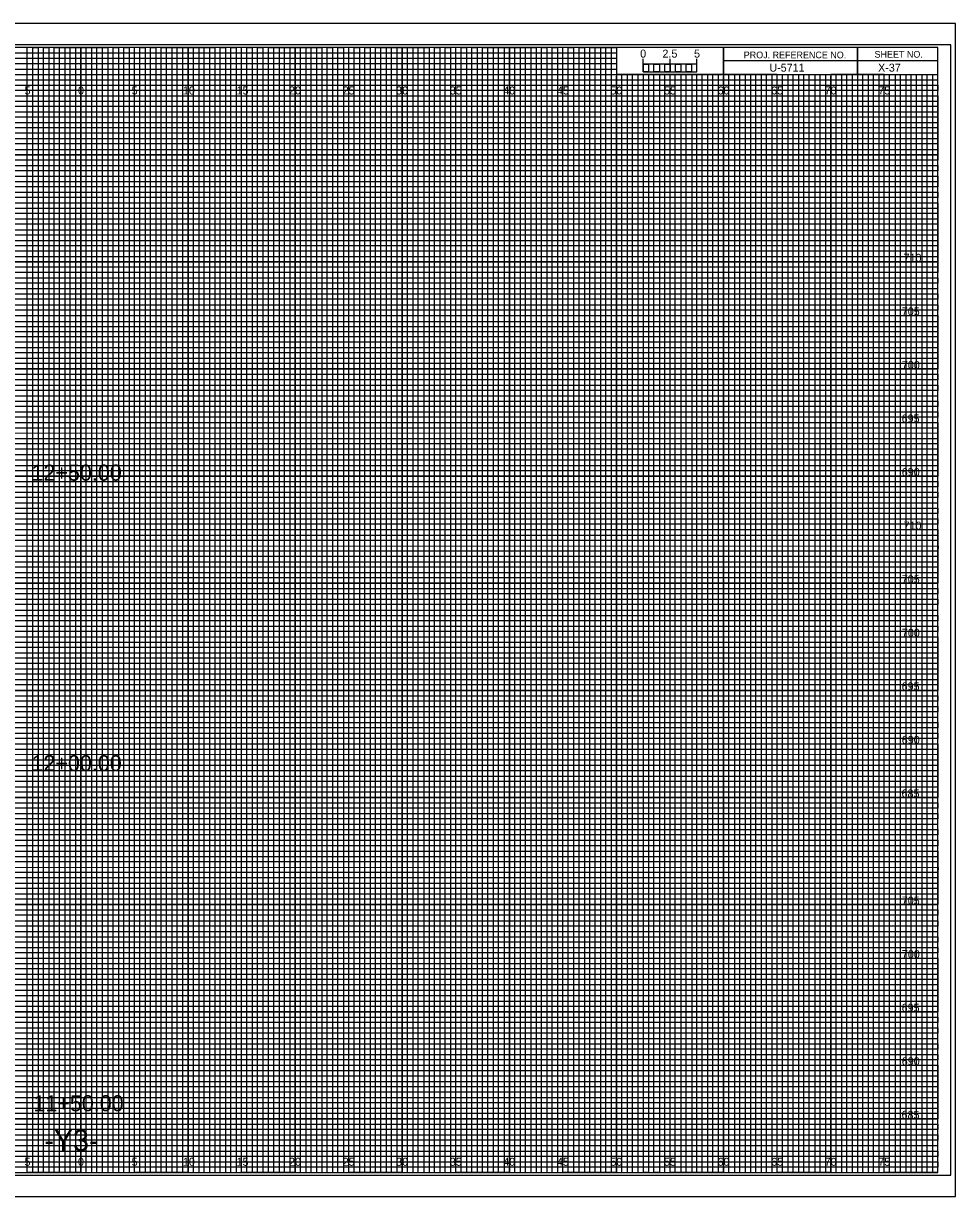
# Model space of a CAD drawing. Extents: x -7 to 162, y 108 to 217.
# Drawn here: x 74.6 to 161.7, y 107.8 to 217.2 of the extents above; entities that cross this region are included whole.
import ezdxf

# ---------------------------------------------------------------- set-up
doc = ezdxf.new("R2010")
doc.units = 0
for name, color, linetype in [('Exist Cross Section Cell', 7, 'Continuous'), ('Exist XS Ground Line', 7, 'Continuous'), ('Prop CMT Pvmt Course 1', 7, 'Continuous'), ('Prop CMT Pvmt Course 2', 7, 'Continuous'), ('Prop CMT Pvmt Course 3', 7, 'Continuous'), ('Prop CMT Pvmt Surface', 7, 'Continuous'), ('Prop CMT Pvmt Surface Shoulder', 7, 'Continuous'), ('Prop CMT Shld Paved Course 1', 7, 'Continuous'), ('Prop CMT Shld Paved Course 2', 7, 'Continuous'), ('Prop CMT Shld Paved Course 3', 7, 'Continuous'), ('Prop CMT Slope Grass', 7, 'Continuous'), ('Prop CMT Subgrade Earthwork', 7, 'Continuous'), ('Prop XS Ditch Standard Text', 7, 'Continuous'), ('Prop XS SE Text', 7, 'Continuous'), ('Prop XS Side Slope Text', 7, 'Continuous'), ('Scratch_Level_7', 7, 'Continuous'), ('Scratch_Level_8', 7, 'Continuous')]:
    doc.layers.add(name, color=color, linetype=linetype)

msp = doc.modelspace()

# ---------------------------------------------------------------- linework, layer by layer
at = {"layer": 'Exist XS Ground Line'}
for p, q in [((75, 215), (70, 215)), ((75, 110), (75, 215)), ((85, 215), (80, 215)), ((80, 215), (80, 110)), ((85, 110), (85, 215)), ((95, 215), (90, 215)), ((90, 215), (90, 110)), ((95, 110), (95, 215)), ((105, 215), (100, 215)), ((100, 215), (100, 110)), ((105, 110), (105, 215)), ((115, 215), (110, 215)), ((110, 215), (110, 110)), ((115, 110), (115, 215)), ((125, 215), (120, 215)), ((120, 215), (120, 110)), ((125, 110), (125, 215)), ((130, 215), (130, 110)), ((135, 110), (135, 212.5)), ((145, 212.5), (140, 212.5)), ((140, 212.5), (140, 110)), ((145, 110), (145, 212.5)), ((155, 212.5), (150, 212.5)), ((150, 212.5), (150, 110)), ((155, 110), (155, 212.5)), ((80, 110), (75, 110)), ((90, 110), (85, 110)), ((100, 110), (95, 110)), ((110, 110), (105, 110)), ((120, 110), (115, 110)), ((130, 110), (125, 110)), ((140, 110), (135, 110)), ((150, 110), (145, 110)), ((160, 110), (155, 110)), ((160, 110), (160, 110))]:
    msp.add_line(p, q, dxfattribs=at)
for points in [[(0, 210), (160, 210), (160, 205), (0, 205)], [(0, 200), (160, 200), (160, 195), (0, 195)], [(0, 190), (160, 190), (160, 185), (0, 185)], [(0, 180), (160, 180), (160, 175), (0, 175)], [(0, 170), (160, 170), (160, 165), (0, 165)], [(0, 160), (160, 160), (160, 155), (0, 155)], [(0, 150), (160, 150), (160, 145), (0, 145)], [(0, 140), (160, 140), (160, 135), (0, 135)], [(0, 130), (160, 130), (160, 125), (0, 125)], [(0, 120), (160, 120), (160, 115), (0, 115)]]:
    msp.add_lwpolyline(points, dxfattribs=at)
at = {"layer": 'Prop CMT Pvmt Course 2'}
for p, q in [((132.5, 212.75), (132.5, 213.95)), ((132.5, 213.45), (132.5, 213.95)), ((135, 212.75), (135, 213.95)), ((137.5, 212.75), (137.5, 213.95)), ((137.5, 213.45), (137.5, 213.95))]:
    msp.add_line(p, q, dxfattribs=at)
for points in [[(137.5, 213.45), (132.5, 213.45), (132.5, 212.75), (137.5, 212.75)], [(132.5, 213.45), (133, 213.45), (133, 212.75), (132.5, 212.75)], [(133.5, 213.45), (134, 213.45), (134, 212.75), (133.5, 212.75)], [(134.5, 213.45), (135, 213.45), (135, 212.75), (134.5, 212.75)], [(135.5, 213.45), (136, 213.45), (136, 212.75), (135.5, 212.75)], [(136.5, 213.45), (137, 213.45), (137, 212.75), (136.5, 212.75)]]:
    msp.add_lwpolyline(points, close=True, dxfattribs=at)
at = {"layer": 'Prop CMT Pvmt Course 3'}
msp.add_lwpolyline([(-6.7, 107.75), (161.65, 107.75), (161.65, 217.25), (-6.7, 217.25)], close=True, dxfattribs=at)
at = {"layer": 'Prop CMT Pvmt Surface'}
for p, q in [((75, 110), (75, 215)), ((80, 110), (80, 215)), ((85, 110), (85, 215)), ((90, 110), (90, 215)), ((95, 110), (95, 215)), ((100, 110), (100, 215)), ((105, 110), (105, 215)), ((110, 110), (110, 215)), ((115, 110), (115, 215)), ((120, 110), (120, 215)), ((125, 110), (125, 215)), ((130, 110), (130, 212.34)), ((135, 110), (135, 212.34)), ((140, 110), (140, 212.34)), ((145, 110), (145, 212.34)), ((150, 110), (150, 212.34)), ((155, 110), (155, 212.34)), ((0, 210), (160, 210)), ((0, 205), (160, 205)), ((0, 200), (160, 200)), ((0, 195), (160, 195)), ((0, 190), (160, 190)), ((0, 185), (160, 185)), ((0, 180), (160, 180)), ((0, 175), (160, 175)), ((0, 170), (160, 170)), ((0, 165), (160, 165)), ((0, 160), (160, 160)), ((0, 155), (160, 155)), ((0, 150), (160, 150)), ((0, 145), (160, 145)), ((0, 140), (160, 140)), ((0, 135), (160, 135)), ((0, 130), (160, 130)), ((0, 125), (160, 125)), ((0, 120), (160, 120)), ((0, 115), (160, 115))]:
    msp.add_line(p, q, dxfattribs=at)
at = {"layer": 'Prop CMT Pvmt Surface Shoulder'}
for p, q in [((161.65, 217.25), (-6.7, 217.25)), ((-6.7, 107.75), (161.65, 107.75))]:
    msp.add_line(p, q, dxfattribs=at)
at = {"layer": 'Prop CMT Shld Paved Course 1'}
for p, q in [((0, 214.5), (130, 214.5)), ((130, 213.99), (0, 213.99)), ((130, 214.5), (130, 213.99)), ((0, 213.5), (130, 213.5)), ((130, 212.94), (0, 212.94)), ((130, 213.5), (130, 212.94)), ((0, 212), (160, 212))]:
    msp.add_line(p, q, dxfattribs=at)
for points in [[(0, 211.5), (135, 211.5), (160, 211.5), (160, 211), (0, 211)], [(0, 210.5), (160, 210.5), (160, 209.5), (0, 209.5)], [(0, 209), (160, 209), (160, 208.5), (0, 208.49)], [(0, 208), (160, 208), (160, 207), (0, 207)], [(0, 206.5), (160, 206.5), (160, 206), (0, 206)], [(0, 205.5), (160, 205.5), (160, 204.5), (0, 204.5)], [(0, 204), (160, 204), (160, 203.5), (0, 203.5)], [(0, 203), (160, 203), (160, 202), (0, 202)], [(0, 201.5), (160, 201.5), (160, 201), (0, 201)], [(0, 200.5), (160, 200.5), (160, 199.5), (0, 199.5)], [(0, 199), (160, 199), (160, 198.5), (0, 198.5)], [(0, 198), (160, 198), (160, 196.97), (160, 196.5), (160, 196), (0, 196)], [(0, 197), (160, 197), (160, 196.5), (0, 196.5)], [(0, 195.5), (160, 195.5), (160, 194.5), (0, 194.52)], [(0, 194.52), (160, 194.5), (160, 194), (0, 194)], [(0, 193.5), (160, 193.5), (160, 193), (0, 193)], [(0, 192), (160, 192), (160, 191.5), (0, 191.5)], [(0, 191), (160, 191), (160, 190.5), (0, 190.5)], [(-0.04, 189.44), (160, 189.44), (160, 188.94), (-0.04, 188.94)], [(0, 188.5), (160, 188.5), (160, 188), (0, 188)], [(0, 187), (160, 187), (160, 186.5), (0, 186.5)], [(0, 186), (160, 186), (160, 185.5), (0, 185.5)], [(0, 184.5), (160, 184.5), (160, 184), (0, 184)], [(0, 183.5), (160, 183.5), (160, 183), (0, 183)], [(0, 182), (160, 182), (160, 181.5), (0, 181.5)], [(0, 181), (160, 181), (160, 180.5), (0, 180.5)], [(0, 179.5), (160, 179.5), (160, 178.99), (0, 179)], [(0, 178.5), (160, 178.5), (160, 178), (0, 178)], [(0, 177), (160, 177), (160, 176.5), (0, 176.5)], [(0, 176), (160, 176), (160, 175.5), (0, 175.5)], [(0, 174.5), (160, 174.5), (160, 174), (0, 174)], [(0, 173.5), (160, 173.5), (160, 173), (0, 173)], [(0, 172), (160, 172), (160, 171.5), (0, 171.5)], [(0, 171), (160, 171), (160, 170.5), (0, 170.5)], [(0, 169.5), (160, 169.5), (160, 169), (0, 169)], [(0, 168.5), (160.03, 168.46), (160, 168), (0, 168)], [(0, 167), (160, 167), (160, 166.5), (0, 166.5)], [(0, 166), (160, 166), (160, 165.5), (0, 165.5)], [(0, 164.5), (160, 164.5), (160, 164), (0, 164)], [(0, 163.5), (160, 163.5), (160, 163), (0, 163)], [(0, 162), (160, 162), (160, 161.5), (0, 161.5)], [(0, 161), (160, 161), (160, 160.5), (0, 160.5)], [(0, 159.5), (160, 159.5), (160, 159), (0, 159)], [(0, 158.5), (160, 158.5), (160, 158), (0, 158)], [(0, 157), (160, 157), (160, 156.5), (0, 156.5)], [(0, 156), (160, 156), (160, 155.5), (0, 155.5)], [(0, 154.5), (160, 154.5), (160, 154), (0, 154)], [(0, 153.5), (160, 153.5), (160, 153), (0, 153)], [(0, 152), (160, 152), (160, 151.5), (0, 151.5)], [(0, 151), (160, 151), (160, 150.5), (0, 150.5)], [(0, 149.5), (160, 149.5), (160, 148.99), (0, 149)], [(0, 148.5), (160, 148.5), (160, 148), (0, 148)], [(0, 147), (160, 147), (160, 146.5), (0, 146.5)], [(0, 146), (160, 146), (160, 145.5), (0, 145.5)], [(0, 144.5), (160, 144.5), (160, 144), (0, 144)], [(0, 143.5), (160, 143.5), (160, 143), (0, 143)], [(0, 142), (160, 142), (160, 141.5), (0, 141.5)], [(0, 141), (160, 141), (160, 140.5), (0, 140.5)], [(0, 139.5), (160, 139.5), (160, 139), (0, 139)], [(0, 138.5), (160.03, 138.46), (160, 138), (0, 138)], [(0, 137), (160, 137), (160, 136.5), (0, 136.5)], [(0, 136), (160, 136), (160, 135.5), (0, 135.5)], [(0, 134.5), (160, 134.5), (160, 134), (0, 134)], [(0, 133.5), (160, 133.5), (160, 133), (0, 133)], [(0, 132), (160, 132), (160, 131.5), (0, 131.5)], [(0, 131), (160, 131), (160, 130.5), (0, 130.5)], [(0, 129.5), (160, 129.5), (160, 129), (0, 129)], [(0, 128.5), (160, 128.5), (160, 128), (0, 128)], [(0, 127), (160, 127), (160, 126.5), (0, 126.5)], [(0, 126), (160, 126), (160, 125.5), (0, 125.5)], [(0, 124.5), (160, 124.5), (160, 124), (0, 124)], [(0, 123.5), (160, 123.5), (160, 123), (0, 123)], [(0, 122), (160, 122), (160, 121.5), (0, 121.5)], [(0, 121), (160, 121), (160, 120.5), (0, 120.5)], [(0, 119.5), (160, 119.5), (160, 119), (0, 119)], [(0, 118.5), (160, 118.5), (160, 118), (0, 118)], [(0, 117), (160, 117), (160, 116.5), (0, 116.5)], [(0, 116), (160, 116), (160, 115.5), (0, 115.5)], [(0, 114.5), (160, 114.5), (160, 114), (0, 114)], [(0, 113.5), (160, 113.5), (160, 113), (0, 113)], [(0, 112), (160, 112), (160, 111.5), (0, 111.5)], [(0, 111), (160, 111), (160, 110.5), (0, 110.5)]]:
    msp.add_lwpolyline(points, dxfattribs=at)
at = {"layer": 'Prop CMT Shld Paved Course 2'}
for p, q in [((152.5, 215), (152.5, 212.5)), ((152.5, 212.5), (152.5, 215)), ((160, 213.75), (140, 213.75)), ((140, 213.75), (140, 212.5)), ((140, 212.5), (160, 212.5))]:
    msp.add_line(p, q, dxfattribs=at)
for points in [[(160, 215), (0, 215), (0, 110), (160, 110)], [(140, 215), (130, 215), (130, 212.52), (140, 212.52)], [(160, 215), (140, 215), (140, 212.5), (160, 212.5)]]:
    msp.add_lwpolyline(points, close=True, dxfattribs=at)
at = {"layer": 'Prop CMT Shld Paved Course 3'}
for p, q in [((133.5, 212.5), (133, 212.5)), ((133, 212.5), (133, 110)), ((133.5, 110), (133.5, 212.5)), ((134.5, 212.5), (134, 212.5)), ((134, 212.5), (134, 110)), ((134.5, 110), (134.5, 212.5)), ((133, 110), (132.5, 110)), ((134, 110), (133.5, 110))]:
    msp.add_line(p, q, dxfattribs=at)
for points in [[(75, 110), (75.5, 110), (75.5, 215), (76, 215), (76, 110)], [(76, 110), (76.5, 110), (76.5, 215), (77, 215), (77, 110)], [(77.5, 110), (78, 110), (78, 215), (78.5, 215), (78.5, 110)], [(78.5, 110), (79, 110), (79, 215), (79.5, 215), (79.5, 110)], [(80, 110), (80.5, 110), (80.5, 215), (81, 215), (81, 110)], [(81, 110), (81.5, 110), (81.5, 215), (82, 215), (82, 110)], [(82.5, 110), (83, 110), (83, 215), (83.5, 215), (83.5, 110)], [(83.5, 110), (84, 110), (84, 215), (84.5, 215), (84.5, 110)], [(85, 110), (85.5, 110), (85.5, 215), (86, 215), (86, 110)], [(86, 110), (86.5, 110), (86.5, 215), (87, 215), (87, 110)], [(87.5, 110), (88, 110), (88, 215), (88.5, 215), (88.5, 110)], [(88.5, 110), (89, 110), (89, 215), (89.5, 215), (89.5, 110)], [(90, 110), (90.5, 110), (90.5, 215), (91, 215), (91, 110)], [(91, 110), (91.5, 110), (91.5, 215), (92, 215), (92, 110)], [(92.5, 110), (93, 110), (93, 215), (93.5, 215), (93.5, 110)], [(93.5, 110), (94, 110), (94, 215), (94.5, 215), (94.5, 110)], [(95, 110), (95.5, 110), (95.5, 215), (96, 215), (96, 110)], [(96, 110), (96.5, 110), (96.5, 215), (97, 215), (97, 110)], [(97.5, 110), (98, 110), (98, 215), (98.5, 215), (98.5, 110)], [(98.5, 110), (99, 110), (99, 215), (99.5, 215), (99.5, 110)], [(100, 110), (100.5, 110), (100.5, 215), (101, 215), (101, 110)], [(101, 110), (101.5, 110), (101.5, 215), (102, 215), (102, 110)], [(102.5, 110), (103, 110), (103, 215), (103.5, 215), (103.5, 110)], [(103.5, 110), (104, 110), (104, 215), (104.5, 215), (104.5, 110)], [(105, 110), (105.5, 110), (105.5, 215), (106, 215), (106, 110)], [(106, 110), (106.5, 110), (106.5, 215), (107, 215), (107, 110)], [(107.5, 110), (108, 110), (108, 215), (108.5, 215), (108.5, 110)], [(108.5, 110), (109, 110), (109, 215), (109.5, 215), (109.5, 110)], [(110, 110), (110.5, 110), (110.5, 215), (111, 215), (111, 110)], [(111, 110), (111.5, 110), (111.5, 215), (112, 215), (112, 110)], [(112.5, 110), (113, 110), (113, 215), (113.5, 215), (113.5, 110)], [(113.5, 110), (114, 110), (114, 215), (114.5, 215), (114.5, 110)], [(115, 110), (115.5, 110), (115.5, 215), (116, 215), (116, 110)], [(116, 110), (116.5, 110), (116.5, 215), (117, 215), (117, 110)], [(117.5, 110), (118, 110), (118, 215), (118.5, 215), (118.5, 110)], [(118.5, 110), (119, 110), (119, 215), (119.5, 215), (119.5, 110)], [(120, 110), (120.5, 110), (120.5, 215), (121, 215), (121, 110)], [(121, 110), (121.5, 110), (121.5, 215), (122, 215), (122, 110)], [(122.5, 110), (123, 110), (123, 215), (123.5, 215), (123.5, 110)], [(123.5, 110), (124, 110), (124, 215), (124.5, 215), (124.5, 110)], [(125, 110), (125.5, 110), (125.5, 215), (126, 215), (126, 110)], [(126, 110), (126.5, 110), (126.5, 215), (127, 215), (127, 110)], [(127.5, 110), (128, 110), (128, 215), (128.5, 215), (128.5, 110)], [(128.5, 110), (129, 110), (129, 215), (129.5, 215), (129.5, 110)], [(130, 110), (130.5, 110), (130.5, 212.5), (131.01, 212.5), (131.01, 110)], [(131, 110), (131.5, 110), (131.5, 212.5), (132, 212.5), (132, 110)], [(135, 110), (135.49, 110), (135.49, 212.5), (136, 212.5), (136, 110)], [(136, 110), (136.5, 110), (136.5, 212.5), (137.03, 212.5), (137.03, 110)], [(137.5, 110), (138, 110), (138, 212.5), (138.5, 212.5), (138.5, 110)], [(138.5, 110), (139, 110), (139, 212.5), (139.5, 212.5), (139.5, 110)], [(140, 110), (140.5, 110), (140.5, 212.5), (141, 212.5), (141, 110)], [(141, 110), (141.5, 110), (141.5, 212.5), (142, 212.5), (142, 110)], [(142.5, 110), (143, 110), (143, 212.5), (143.5, 212.5), (143.5, 110)], [(143.5, 110), (144, 110), (144, 212.5), (144.5, 212.5), (144.5, 110)], [(145, 110), (145.5, 110), (145.5, 212.5), (146, 212.5), (146, 110)], [(146, 110), (146.5, 110), (146.5, 212.5), (147, 212.5), (147, 110)], [(147.5, 110), (148, 110), (148, 212.5), (148.5, 212.5), (148.5, 110)], [(148.5, 110), (149, 110), (149, 212.5), (149.5, 212.5), (149.5, 110)], [(150, 110), (150.5, 110), (150.5, 212.5), (151, 212.5), (151, 110)], [(151, 110), (151.5, 110), (151.5, 212.5), (152, 212.5), (152, 110)], [(152.5, 110), (153, 110), (153, 212.5), (153.5, 212.5), (153.5, 110)], [(153.5, 110), (154, 110), (154, 212.5), (154.5, 212.5), (154.5, 110)], [(155, 110), (155.5, 110), (155.5, 212.5), (156, 212.5), (156, 110)], [(156, 110), (156.5, 110), (156.5, 212.5), (157, 212.5), (157, 110)], [(157.5, 110), (158, 110), (158, 212.5), (158.5, 212.5), (158.5, 110)], [(158.5, 110), (159, 110), (159, 212.5), (159.5, 212.5), (159.5, 110)]]:
    msp.add_lwpolyline(points, dxfattribs=at)
at = {"layer": 'Prop CMT Subgrade Earthwork'}
msp.add_lwpolyline([(-5.4, 109.75), (161.2, 109.75), (161.2, 215.25), (-5.4, 215.25)], close=True, dxfattribs=at)
at = {"layer": 'Scratch_Level_8'}
for points in [[(72.5, 110), (77.5, 110), (77.5, 215), (82.5, 215), (82.5, 110), (87.5, 110), (87.5, 215), (92.5, 215), (92.5, 110), (97.5, 110), (97.5, 215), (102.5, 215), (102.5, 110), (107.5, 110), (107.5, 215), (112.5, 215), (112.5, 110), (117.5, 110), (117.5, 215), (122.5, 215), (122.5, 110), (127.5, 110), (127.5, 215), (129.97, 215), (130, 215), (130, 212.5), (132.5, 212.5), (132.5, 110), (137.5, 110), (137.5, 212.5), (142.5, 212.5), (142.5, 110), (147.5, 110), (147.5, 212.5), (152.5, 212.5), (152.5, 110), (157.5, 110), (157.5, 212.5)], [(0, 212.5), (137.5, 212.5)], [(0, 202.5), (160, 202.5), (160, 207.5), (0, 207.5)], [(0, 192.5), (160, 192.5), (160, 197.5), (0, 197.5)], [(0, 182.5), (160, 182.5), (160, 187.5), (0, 187.5)], [(0, 172.5), (160, 172.5), (160, 177.5), (0, 177.5)], [(0, 162.5), (160, 162.5), (160, 167.5), (0, 167.5)], [(0, 152.5), (160, 152.5), (160, 157.5), (0, 157.5)], [(0, 142.5), (160, 142.5), (160, 147.5), (0, 147.5)], [(0, 132.5), (160, 132.5), (160, 137.5), (0, 137.5)], [(0, 122.5), (160, 122.5), (160, 127.5), (0, 127.5)], [(0, 112.5), (160, 112.5), (160, 117.5), (0, 117.5)]]:
    msp.add_lwpolyline(points, dxfattribs=at)

# ---------------------------------------------------------------- texts
at = {"layer": 'Exist Cross Section Cell'}
for s, p in [('5', (74.74, 210.62)), ('0', (79.73, 210.62)), ('0', (79.73, 210.62)), ('5', (84.74, 210.62)), ('10', (89.52, 210.62)), ('15', (94.53, 210.62)), ('20', (99.43, 210.62)), ('25', (104.44, 210.62)), ('30', (109.43, 210.62)), ('35', (114.44, 210.62)), ('40', (119.43, 210.62)), ('45', (124.44, 210.62)), ('50', (129.43, 210.62)), ('55', (134.44, 210.62)), ('60', (139.43, 210.62)), ('65', (144.44, 210.62)), ('70', (149.43, 210.62)), ('75', (154.44, 210.62)), ('5', (74.74, 110.62)), ('0', (79.73, 110.62)), ('0', (79.73, 110.62)), ('5', (84.74, 110.62)), ('10', (89.52, 110.62)), ('15', (94.53, 110.62)), ('20', (99.43, 110.62)), ('25', (104.44, 110.62)), ('30', (109.43, 110.62)), ('35', (114.44, 110.62)), ('40', (119.43, 110.62)), ('45', (124.44, 110.62)), ('50', (129.43, 110.62)), ('55', (134.44, 110.62)), ('60', (139.43, 110.62)), ('65', (144.44, 110.62)), ('70', (149.43, 110.62)), ('75', (154.44, 110.62))]:
    msp.add_text(s, height=0.75, dxfattribs=at).set_placement(p)
at = {"layer": 'Prop CMT Pvmt Course 1'}
for s, p in [('710', (156.8, 195)), ('705', (156.63, 190)), ('700', (156.64, 185)), ('695', (156.62, 180)), ('690', (156.63, 175)), ('710', (156.8, 170)), ('705', (156.63, 165)), ('700', (156.64, 160)), ('695', (156.62, 155)), ('690', (156.63, 150)), ('685', (156.61, 145)), ('705', (156.63, 135)), ('700', (156.64, 130)), ('695', (156.62, 125)), ('690', (156.63, 120)), ('685', (156.61, 115))]:
    msp.add_text(s, height=0.75, dxfattribs=at).set_placement(p)
at = {"layer": 'Prop CMT Pvmt Course 2'}
msp.add_text('0', height=0.75, dxfattribs=at).set_placement((132.21, 214.06))
at = {"layer": 'Prop CMT Shld Paved Course 2'}
for s, p in [('PROJ. REFERENCE NO.', (141.88, 214)), ('SHEET NO.', (154.09, 214.06))]:
    msp.add_text(s, height=0.625, dxfattribs=at).set_placement(p)
at = {"layer": 'Prop CMT Slope Grass'}
for s, p in [('12+50.00', (75.39, 174.57)), ('12+00.00', (75.39, 147.45)), ('11+50.00', (75.57, 115.71))]:
    msp.add_text(s, height=1.5, dxfattribs=at).set_placement(p)
at = {"layer": 'Prop XS Ditch Standard Text'}
for s, p in [('2.5', (134.29, 214.06)), ('5', (137.24, 214.06))]:
    msp.add_text(s, height=0.75, dxfattribs=at).set_placement(p)
at = {"layer": 'Prop XS SE Text'}
msp.add_text('-Y3-', height=2, dxfattribs=at).set_placement((76.59, 112))
at = {"layer": 'Prop XS Side Slope Text'}
msp.add_text('U-5711', height=0.75, dxfattribs=at).set_placement((144.27, 212.75))
at = {"layer": 'Scratch_Level_7'}
msp.add_text('X-37', height=0.75, dxfattribs=at).set_placement((154.42, 212.75))

doc.saveas('drawing.dxf')
